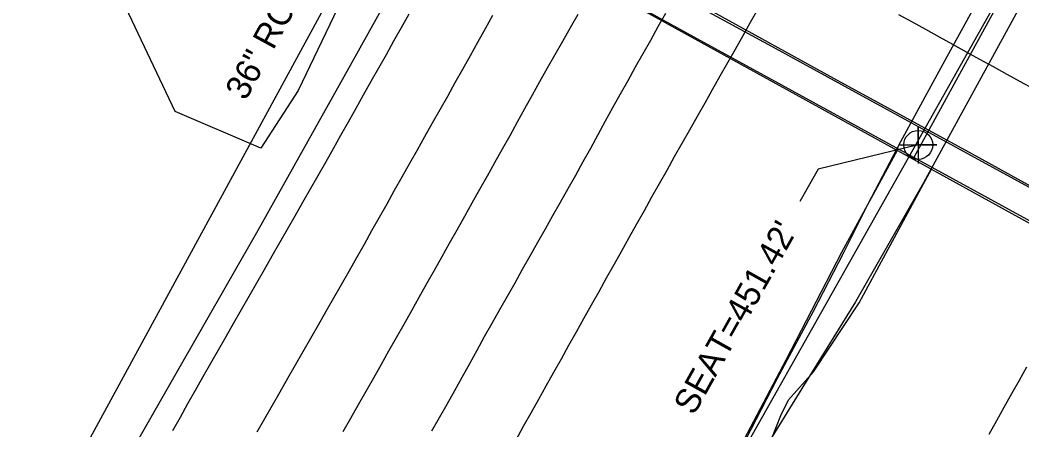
# Model space of a CAD drawing. Extents: x 2074109 to 2077820, y 741079 to 746031.
# Drawn here: x 2075369.9 to 2075532.2, y 743274.4 to 743340.7 of the extents above; entities that cross this region are included whole.
import ezdxf

# ---------------------------------------------------------------- set-up
doc = ezdxf.new("R2010")
doc.units = 0
for name, color, linetype in [('Exist Guardrail', 7, 'Continuous'), ('Exist Horizontal Alignment', 7, 'Continuous'), ('Exist Roads EOP', 7, 'Continuous'), ('Exist Roads EOP Other', 7, 'Continuous'), ('Exist Roads EOT', 7, 'Continuous'), ('Exist Structure Major Bridge Seam', 7, 'Continuous'), ('Exist Structure Major Bridge Seat Cogo Point CELL', 7, 'Continuous'), ('Exist Structure Major Bridge Seat Leader', 7, 'Continuous'), ('Exist Structure Major Bridge Seat Top Elevation', 7, 'Continuous'), ('Exist Structure Major Deck Tunnel Box Culvert', 7, 'Continuous'), ('Exist Structure Minor Pipes RCP 36 Inch', 7, 'Continuous'), ('Exist Structure Minor Pipes RCP 36 Inch Text', 7, 'Continuous'), ('Exist Vegetation Woods Line', 7, 'Continuous')]:
    doc.layers.add(name, color=color, linetype=linetype)

msp = doc.modelspace()

# ---------------------------------------------------------------- linework, layer by layer
at = {"layer": 'Exist Guardrail'}
msp.add_lwpolyline([(2075512, 743319.65), (2075502.94, 743303.13), (2075493.94, 743285.73), (2075484.57, 743267.94), (2075467.67, 743236.71), (2075464.85, 743230.79), (2075466.28, 743230.1), (2075471.4, 743239.22), (2075491.65, 743272.95), (2075493.15, 743276.78), (2075494.36, 743279.31), (2075498.42, 743283.85), (2075505.82, 743294.97), (2075516.25, 743314.25), (2075517.53, 743316.6)], dxfattribs=at)
at = {"layer": 'Exist Horizontal Alignment'}
msp.add_line((2074886.11, 742205.34), (2075575.25, 743427.42), dxfattribs=at)
at = {"layer": 'Exist Roads EOP'}
for points in [[(2075559.5, 743577.98), (2075554.8, 743568.73), (2075547.03, 743553.55), (2075539.18, 743539.38), (2075530.34, 743523.8), (2075517.96, 743501.62), (2075504.54, 743477.52), (2075492.04, 743456), (2075482.7, 743440.16), (2075465.16, 743408.97), (2075448.94, 743380.02), (2075438.36, 743361.14), (2075432.82, 743350.24), (2075423.13, 743332.91), (2075408.43, 743306.71), (2075394.81, 743282.87), (2075378.9, 743255.03), (2075364.05, 743228.71), (2075347.68, 743199.79), (2075332.2, 743172.4), (2075317.22, 743145.53), (2075301.28, 743116.93)], [(2075629.48, 743509.98), (2075612.24, 743485.93), (2075603.42, 743470.69), (2075597.29, 743458.57), (2075588.31, 743442.87), (2075576.16, 743421.96), (2075567.04, 743406.6), (2075558.96, 743392.83), (2075547.09, 743371), (2075533.33, 743345.7), (2075516.25, 743314.4), (2075505.25, 743295.15), (2075496.54, 743281.14), (2075486.37, 743264.69)], [(2075486.59, 743271.21), (2075492.62, 743282.79), (2075498.41, 743293.66), (2075503.35, 743303.11), (2075507.27, 743311), (2075512.55, 743321.1), (2075520.08, 743334.84), (2075528.48, 743350.15), (2075537.18, 743366.11), (2075545.57, 743381.57), (2075553.44, 743396.13), (2075561.87, 743411.12), (2075571.26, 743427.01), (2075580.6, 743442.44), (2075589.42, 743456.78), (2075596.67, 743468.69), (2075601.96, 743477.67), (2075605.92, 743484.73), (2075608.84, 743490.35), (2075611.2, 743495.58), (2075613.21, 743500.83), (2075614.86, 743505.48)]]:
    msp.add_lwpolyline(points, dxfattribs=at)
at = {"layer": 'Exist Roads EOP Other'}
for points in [[(2075366.87, 743399.63), (2075391.52, 743386.11), (2075399.31, 743381.63), (2075400.42, 743380.9), (2075400.42, 743380.9), (2075417.05, 743371.88), (2075424.34, 743367.81), (2075437.43, 743360.73), (2075449.67, 743354.08), (2075462.75, 743347.04), (2075479.55, 743337.75), (2075493.27, 743330.26), (2075511.78, 743320.13), (2075532.97, 743308.52), (2075543.32, 743302.78), (2075555.58, 743296.07), (2075570.56, 743287.96), (2075581.08, 743282.13), (2075591.83, 743276.3), (2075602.54, 743270.44)], [(2075618.54, 743267.07), (2075601.14, 743276.62), (2075583.53, 743286.17), (2075564.08, 743296.86), (2075539.72, 743310.19), (2075523.4, 743319.09), (2075507.55, 743327.8), (2075492.26, 743336.14), (2075475.25, 743345.43), (2075460.95, 743353.21), (2075441.94, 743363.59), (2075425.56, 743372.59), (2075411.83, 743380.02), (2075402.45, 743385.14)]]:
    msp.add_lwpolyline(points, dxfattribs=at)
at = {"layer": 'Exist Roads EOT'}
for points in [[(2075489.44, 743342.52), (2075488.2, 743340.35), (2075486.97, 743338.17), (2075485.74, 743335.99), (2075484.51, 743333.82), (2075483.28, 743331.64), (2075482.05, 743329.47), (2075480.82, 743327.29), (2075479.59, 743325.12), (2075478.36, 743322.94), (2075477.12, 743320.77), (2075475.89, 743318.59), (2075474.66, 743316.41), (2075473.43, 743314.24), (2075472.21, 743312.06), (2075470.99, 743309.88), (2075469.77, 743307.7), (2075468.54, 743305.52), (2075467.32, 743303.33), (2075466.1, 743301.15), (2075464.88, 743298.97), (2075463.66, 743296.79), (2075462.44, 743294.61), (2075461.21, 743292.43), (2075459.99, 743290.25), (2075458.77, 743288.07), (2075457.55, 743285.89), (2075456.33, 743283.71), (2075455.1, 743281.53), (2075453.88, 743279.35), (2075452.66, 743277.17), (2075451.44, 743274.98), (2075450.22, 743272.8)], [(2075394.68, 743274.34), (2075395.91, 743276.52), (2075397.13, 743278.7), (2075398.36, 743280.88), (2075399.59, 743283.06), (2075400.83, 743285.23), (2075402.07, 743287.39), (2075403.31, 743289.56), (2075404.56, 743291.73), (2075405.8, 743293.9), (2075407.04, 743296.07), (2075408.28, 743298.24), (2075409.52, 743300.41), (2075410.76, 743302.58), (2075412, 743304.75), (2075413.24, 743306.92), (2075414.49, 743309.09), (2075415.73, 743311.26), (2075416.97, 743313.43), (2075418.21, 743315.6), (2075419.45, 743317.77), (2075420.69, 743319.94), (2075421.92, 743322.12), (2075423.14, 743324.3), (2075424.37, 743326.48), (2075425.59, 743328.66), (2075426.82, 743330.84), (2075428.04, 743333.01), (2075429.27, 743335.19), (2075430.5, 743337.37), (2075431.72, 743339.55), (2075432.95, 743341.73)], [(2075408.34, 743274.11), (2075409.58, 743276.28), (2075410.82, 743278.45), (2075412.06, 743280.61), (2075413.31, 743282.78), (2075414.55, 743284.95), (2075415.79, 743287.12), (2075417.03, 743289.29), (2075418.28, 743291.46), (2075419.52, 743293.63), (2075420.76, 743295.8), (2075422, 743297.97), (2075423.24, 743300.14), (2075424.47, 743302.32), (2075425.7, 743304.49), (2075426.92, 743306.67), (2075428.15, 743308.85), (2075429.38, 743311.03), (2075430.61, 743313.2), (2075431.83, 743315.38), (2075433.06, 743317.56), (2075434.29, 743319.74), (2075435.52, 743321.91), (2075436.74, 743324.09), (2075437.97, 743326.27), (2075439.2, 743328.45), (2075440.43, 743330.62), (2075441.65, 743332.8), (2075442.87, 743334.98), (2075444.09, 743337.17), (2075445.31, 743339.35), (2075446.52, 743341.53)], [(2075460.26, 743341.64), (2075459.02, 743339.47), (2075457.79, 743337.29), (2075456.56, 743335.12), (2075455.33, 743332.94), (2075454.09, 743330.77), (2075452.87, 743328.59), (2075451.66, 743326.4), (2075450.45, 743324.21), (2075449.24, 743322.02), (2075448.02, 743319.84), (2075446.8, 743317.66), (2075445.57, 743315.48), (2075444.35, 743313.3), (2075443.12, 743311.13), (2075441.9, 743308.95), (2075440.67, 743306.77), (2075439.45, 743304.59), (2075438.23, 743302.41), (2075437, 743300.23), (2075435.78, 743298.05), (2075434.55, 743295.87), (2075433.33, 743293.69), (2075432.1, 743291.51), (2075430.87, 743289.34), (2075429.64, 743287.16), (2075428.41, 743284.99), (2075427.17, 743282.81), (2075425.94, 743280.64), (2075424.7, 743278.47), (2075423.47, 743276.29), (2075422.23, 743274.12)], [(2075436.65, 743274.26), (2075437.88, 743276.44), (2075439.11, 743278.62), (2075440.34, 743280.8), (2075441.56, 743282.98), (2075442.76, 743285.17), (2075443.97, 743287.36), (2075445.18, 743289.55), (2075446.4, 743291.72), (2075447.63, 743293.9), (2075448.87, 743296.08), (2075450.1, 743298.25), (2075451.33, 743300.43), (2075452.56, 743302.6), (2075453.79, 743304.78), (2075455.02, 743306.95), (2075456.25, 743309.13), (2075457.48, 743311.3), (2075458.72, 743313.48), (2075459.95, 743315.65), (2075461.15, 743317.84), (2075462.35, 743320.04), (2075463.54, 743322.23), (2075464.74, 743324.43), (2075465.96, 743326.61), (2075467.18, 743328.79), (2075468.41, 743330.97), (2075469.63, 743333.15), (2075470.86, 743335.33), (2075472.08, 743337.51), (2075473.3, 743339.69), (2075474.53, 743341.87)], [(2075534.16, 743329.55), (2075531.97, 743330.75), (2075529.77, 743331.95), (2075527.58, 743333.15), (2075525.38, 743334.35), (2075523.2, 743335.56), (2075521.01, 743336.77), (2075518.83, 743337.99), (2075516.63, 743339.19), (2075514.44, 743340.39), (2075512.25, 743341.59)], [(2075526.88, 743273.76), (2075528.1, 743275.94), (2075529.32, 743278.12), (2075530.55, 743280.3), (2075531.77, 743282.48), (2075532.99, 743284.66)]]:
    msp.add_lwpolyline(points, dxfattribs=at)
at = {"layer": 'Exist Structure Major Bridge Seam'}
msp.add_line((2075563.57, 743407.75), (2075514.69, 743318.53), dxfattribs=at)
at = {"layer": 'Exist Structure Major Bridge Seat Cogo Point CELL'}
msp.add_lwpolyline([(2075512.39, 743320.54), (2075518.39, 743320.54), (2075515.39, 743320.54), (2075515.39, 743323.54), (2075515.39, 743317.54)], dxfattribs=at)
msp.add_circle((2075515.39, 743320.54), 2.34, dxfattribs=at)
at = {"layer": 'Exist Structure Major Bridge Seat Leader'}
msp.add_lwpolyline([(2075515.39, 743320.54), (2075499.17, 743316.64), (2075496.24, 743311.4)], dxfattribs=at)
at = {"layer": 'Exist Structure Major Deck Tunnel Box Culvert'}
msp.add_line((2075625.56, 743257.09), (2075399.85, 743381.42), dxfattribs=at)
msp.add_lwpolyline([(2075545.13, 743307.48), (2075524.18, 743319.04), (2075501.74, 743331.29), (2075482.13, 743342.05)], dxfattribs=at)
at = {"layer": 'Exist Structure Minor Pipes RCP 36 Inch'}
msp.add_line((2075364.8, 743242.78), (2075501.91, 743494.72), dxfattribs=at)
at = {"layer": 'Exist Vegetation Woods Line'}
msp.add_lwpolyline([(2075400.11, 743368.42), (2075418.03, 743352.36), (2075421.98, 743344.02), (2075414.98, 743329.35), (2075408.95, 743320), (2075395.05, 743325.94), (2075386.61, 743343.77), (2075388.31, 743356.73), (2075392.05, 743364.2), (2075400.11, 743368.42)], dxfattribs=at)

# ---------------------------------------------------------------- texts
at = {"layer": 'Exist Structure Major Bridge Seat Top Elevation'}
for s, p in [("SEAT=452.32'", (2075364.14, 743337.2)), ("SEAT=451.42'", (2075479.06, 743276.64))]:
    msp.add_text(s, height=4, rotation=60.742, dxfattribs=at).set_placement(p)
at = {"layer": 'Exist Structure Minor Pipes RCP 36 Inch Text'}
msp.add_text('36" RCP', height=4, rotation=61.4446, dxfattribs=at).set_placement((2075406.49, 743327.55))

doc.saveas('drawing.dxf')
